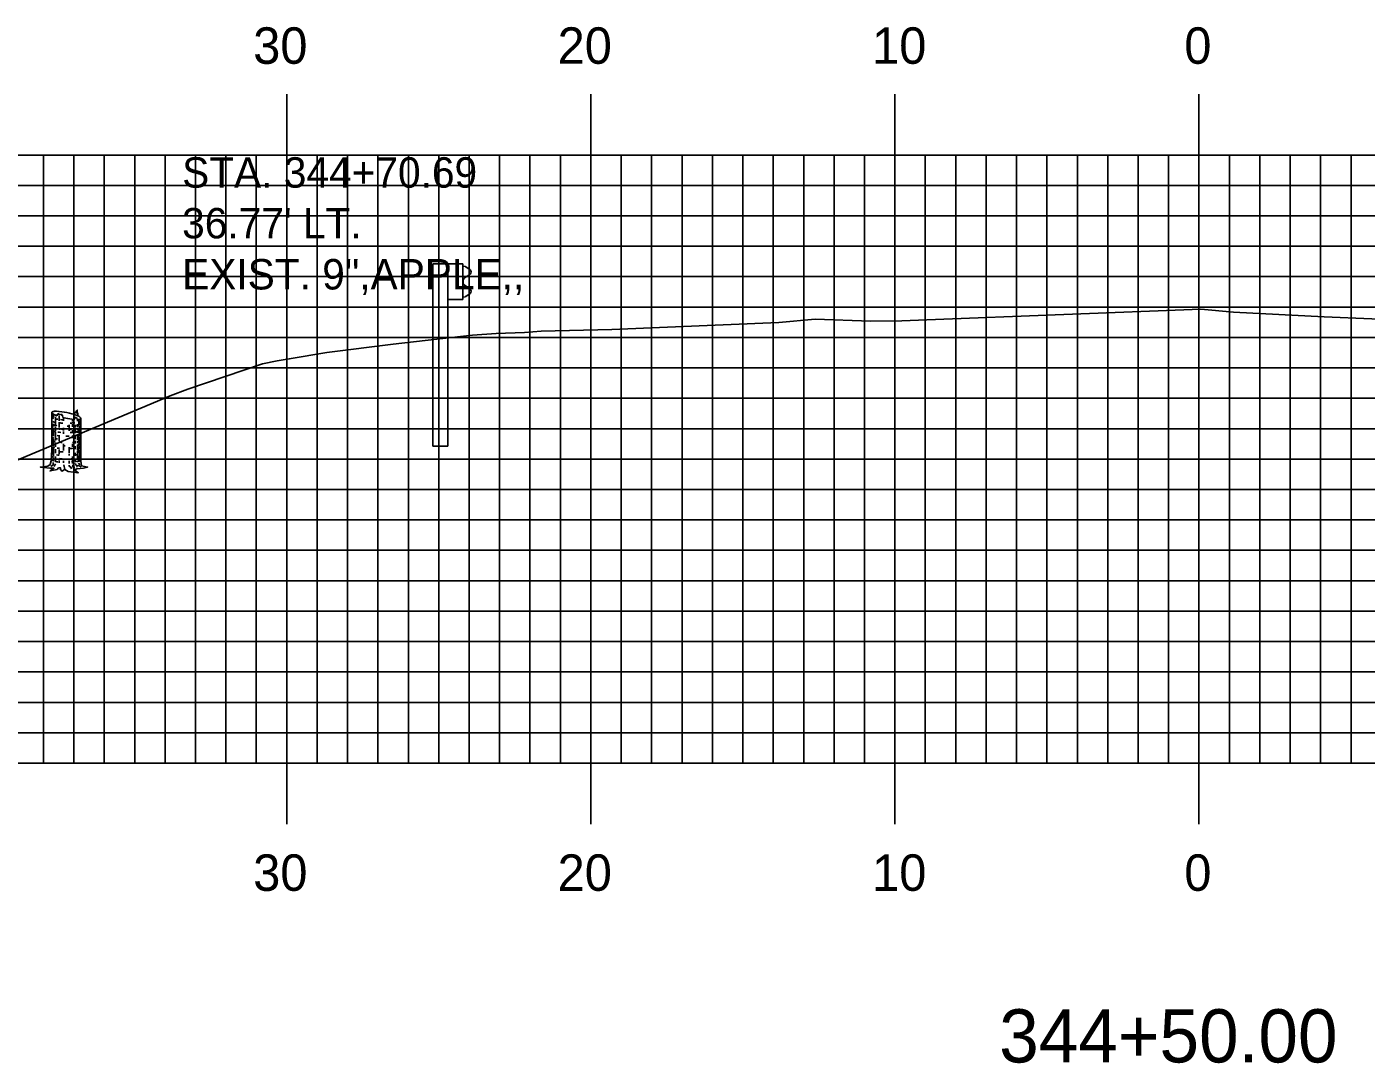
# Model space of a CAD drawing. Extents: x 1825540 to 1825883, y 442591 to 442811.
# Drawn here: x 1825667.33 to 1825711.37, y 442648.8 to 442682.88 of the extents above; entities that cross this region are included whole.
import ezdxf

# ---------------------------------------------------------------- set-up
doc = ezdxf.new("R2010")
doc.units = 0
for name, color, linetype in [('D_Text_Monospaced', 7, 'Continuous'), ('H_V ANNOTATION', 7, 'Continuous'), ('MAJOR', 7, 'Continuous'), ('MINOR', 7, 'Continuous'), ('S_Guardrail_Beam', 7, 'Continuous'), ('S_Roadway_Centerline', 7, 'Continuous'), ('S_Trees_Decid_NonPay', 7, 'Continuous')]:
    doc.layers.add(name, color=color, linetype=linetype)

msp = doc.modelspace()

# ---------------------------------------------------------------- linework, layer by layer
at = {"layer": 'MAJOR'}
for p, q in [((1825675.874, 442680.669), (1825675.874, 442678.665)), ((1825685.874, 442680.669), (1825685.874, 442678.665)), ((1825695.874, 442680.669), (1825695.874, 442678.665)), ((1825705.874, 442680.669), (1825705.874, 442678.665)), ((1825565.874, 442678.665), (1825845.874, 442678.665)), ((1825565.874, 442678.665), (1825845.874, 442678.665)), ((1825675.874, 442658.665), (1825675.874, 442678.665)), ((1825685.874, 442658.665), (1825685.874, 442678.665)), ((1825695.874, 442658.665), (1825695.874, 442678.665)), ((1825705.874, 442658.665), (1825705.874, 442678.665)), ((1825565.874, 442673.665), (1825845.874, 442673.665)), ((1825565.874, 442668.665), (1825845.874, 442668.665)), ((1825565.874, 442663.665), (1825845.874, 442663.665)), ((1825565.874, 442658.665), (1825845.874, 442658.665)), ((1825565.874, 442658.665), (1825845.874, 442658.665)), ((1825675.874, 442656.661), (1825675.874, 442658.665)), ((1825685.874, 442656.661), (1825685.874, 442658.665)), ((1825695.874, 442656.661), (1825695.874, 442658.665)), ((1825705.874, 442656.661), (1825705.874, 442658.665))]:
    msp.add_line(p, q, dxfattribs=at)
at = {"layer": 'MINOR'}
for p, q in [((1825667.874, 442658.665), (1825667.874, 442678.665)), ((1825668.874, 442658.665), (1825668.874, 442678.665)), ((1825669.874, 442658.665), (1825669.874, 442678.665)), ((1825670.874, 442658.665), (1825670.874, 442678.665)), ((1825671.874, 442658.665), (1825671.874, 442678.665)), ((1825672.874, 442658.665), (1825672.874, 442678.665)), ((1825673.874, 442658.665), (1825673.874, 442678.665)), ((1825674.874, 442658.665), (1825674.874, 442678.665)), ((1825676.874, 442658.665), (1825676.874, 442678.665)), ((1825677.874, 442658.665), (1825677.874, 442678.665)), ((1825678.874, 442658.665), (1825678.874, 442678.665)), ((1825679.874, 442658.665), (1825679.874, 442678.665)), ((1825680.874, 442658.665), (1825680.874, 442678.665)), ((1825681.874, 442658.665), (1825681.874, 442678.665)), ((1825682.874, 442658.665), (1825682.874, 442678.665)), ((1825683.874, 442658.665), (1825683.874, 442678.665)), ((1825684.874, 442658.665), (1825684.874, 442678.665)), ((1825686.874, 442658.665), (1825686.874, 442678.665)), ((1825687.874, 442658.665), (1825687.874, 442678.665)), ((1825688.874, 442658.665), (1825688.874, 442678.665)), ((1825689.874, 442658.665), (1825689.874, 442678.665)), ((1825690.874, 442658.665), (1825690.874, 442678.665)), ((1825691.874, 442658.665), (1825691.874, 442678.665)), ((1825692.874, 442658.665), (1825692.874, 442678.665)), ((1825693.874, 442658.665), (1825693.874, 442678.665)), ((1825694.874, 442658.665), (1825694.874, 442678.665)), ((1825696.874, 442658.665), (1825696.874, 442678.665)), ((1825697.874, 442658.665), (1825697.874, 442678.665)), ((1825698.874, 442658.665), (1825698.874, 442678.665)), ((1825699.874, 442658.665), (1825699.874, 442678.665)), ((1825700.874, 442658.665), (1825700.874, 442678.665)), ((1825701.874, 442658.665), (1825701.874, 442678.665)), ((1825702.874, 442658.665), (1825702.874, 442678.665)), ((1825703.874, 442658.665), (1825703.874, 442678.665)), ((1825704.874, 442658.665), (1825704.874, 442678.665)), ((1825706.874, 442658.665), (1825706.874, 442678.665)), ((1825707.874, 442658.665), (1825707.874, 442678.665)), ((1825708.874, 442658.665), (1825708.874, 442678.665)), ((1825709.874, 442658.665), (1825709.874, 442678.665)), ((1825710.874, 442658.665), (1825710.874, 442678.665)), ((1825565.874, 442677.665), (1825845.874, 442677.665)), ((1825565.874, 442676.665), (1825845.874, 442676.665)), ((1825565.874, 442675.665), (1825845.874, 442675.665)), ((1825565.874, 442674.665), (1825845.874, 442674.665)), ((1825565.874, 442672.665), (1825845.874, 442672.665)), ((1825565.874, 442671.665), (1825845.874, 442671.665)), ((1825565.874, 442670.665), (1825845.874, 442670.665)), ((1825565.874, 442669.665), (1825845.874, 442669.665)), ((1825565.874, 442667.665), (1825845.874, 442667.665)), ((1825565.874, 442666.665), (1825845.874, 442666.665)), ((1825565.874, 442665.665), (1825845.874, 442665.665)), ((1825565.874, 442664.665), (1825845.874, 442664.665)), ((1825565.874, 442662.665), (1825845.874, 442662.665)), ((1825565.874, 442661.665), (1825845.874, 442661.665)), ((1825565.874, 442660.665), (1825845.874, 442660.665)), ((1825565.874, 442659.665), (1825845.874, 442659.665))]:
    msp.add_line(p, q, dxfattribs=at)
at = {"layer": 'S_Guardrail_Beam'}
for p, q in [((1825680.68, 442675.086), (1825680.68, 442669.086)), ((1825681.172, 442675.086), (1825680.68, 442675.086)), ((1825681.662, 442675.086), (1825681.172, 442675.086)), ((1825681.172, 442675.086), (1825681.172, 442673.919)), ((1825681.662, 442673.919), (1825681.662, 442675.086)), ((1825681.662, 442675.013), (1825681.744, 442674.999)), ((1825681.904, 442674.749), (1825681.708, 442674.613)), ((1825681.76, 442674.992), (1825681.904, 442674.892)), ((1825681.675, 442674.548), (1825681.675, 442674.457)), ((1825681.708, 442674.393), (1825681.904, 442674.257)), ((1825681.172, 442669.086), (1825681.172, 442673.919)), ((1825681.172, 442673.919), (1825681.662, 442673.919)), ((1825681.744, 442674.007), (1825681.662, 442673.992)), ((1825681.904, 442674.114), (1825681.76, 442674.014)), ((1825681.172, 442669.086), (1825680.68, 442669.086))]:
    msp.add_line(p, q, dxfattribs=at)
for centre, major_axis, start_param, end_param in [((1825681.737, 442674.958), (0.0417, 0), 0.959931, 1.396263), ((1825681.854, 442674.82), (0.0877, 0), 5.323254, 7.243116), ((1825681.754, 442674.548), (-0.0789, 0), 5.323254, 6.283185), ((1825681.754, 442674.457), (-0.0789, 0), 6.283185, 7.243116), ((1825681.854, 442674.185), (0.0877, 0), 5.323254, 7.243116), ((1825681.737, 442674.048), (0.0417, 0), 4.886922, 5.323254)]:
    msp.add_ellipse(centre, major_axis=major_axis, ratio=0.995501, start_param=start_param, end_param=end_param, dxfattribs=at)
at = {"layer": 'S_Roadway_Centerline'}
msp.add_lwpolyline([(1825664.184, 442667.447), (1825672.039, 442670.745), (1825672.623, 442670.97), (1825675.076, 442671.797), (1825675.564, 442671.9), (1825675.957, 442671.958), (1825677.193, 442672.176), (1825679.372, 442672.44), (1825680.812, 442672.609), (1825681.981, 442672.739), (1825682.761, 442672.799), (1825683.698, 442672.826), (1825684.241, 442672.869), (1825686.568, 442672.931), (1825692.058, 442673.155), (1825693.251, 442673.263), (1825695.078, 442673.202), (1825696.1, 442673.21), (1825696.925, 442673.248), (1825705.934, 442673.591), (1825707.009, 442673.494), (1825709.987, 442673.349), (1825713.123, 442673.21)], dxfattribs=at)
at = {"layer": 'S_Trees_Decid_NonPay'}
for p, q in [((1825668.201, 442670.144), (1825668.201, 442670.049)), ((1825668.201, 442669.823), (1825668.201, 442669.74)), ((1825668.269, 442670.057), (1825668.269, 442669.756)), ((1825668.388, 442670.074), (1825668.388, 442669.926)), ((1825668.388, 442669.878), (1825668.388, 442669.709)), ((1825668.535, 442670.028), (1825668.535, 442669.921)), ((1825668.715, 442669.792), (1825668.715, 442669.592)), ((1825668.832, 442669.976), (1825668.832, 442669.897)), ((1825668.832, 442669.81), (1825668.832, 442669.726)), ((1825668.919, 442669.792), (1825668.919, 442669.705)), ((1825668.99, 442669.965), (1825668.99, 442669.913)), ((1825668.99, 442669.81), (1825668.99, 442669.728)), ((1825669.032, 442669.97), (1825669.032, 442669.752)), ((1825669.059, 442669.9), (1825669.059, 442669.818)), ((1825668.201, 442669.67), (1825668.201, 442669.419)), ((1825668.201, 442669.336), (1825668.201, 442669.106)), ((1825668.269, 442669.728), (1825668.269, 442669.596)), ((1825668.269, 442669.562), (1825668.269, 442669.281)), ((1825668.388, 442669.403), (1825668.388, 442669.254)), ((1825668.535, 442669.693), (1825668.535, 442669.606)), ((1825668.535, 442669.571), (1825668.535, 442669.501)), ((1825668.832, 442669.615), (1825668.832, 442669.514)), ((1825668.832, 442669.429), (1825668.832, 442669.353)), ((1825668.919, 442669.635), (1825668.919, 442669.514)), ((1825668.919, 442669.438), (1825668.919, 442669.324)), ((1825668.99, 442669.693), (1825668.99, 442669.619)), ((1825668.99, 442669.592), (1825668.99, 442669.532)), ((1825668.99, 442669.479), (1825668.99, 442669.298)), ((1825669.032, 442669.684), (1825669.032, 442669.532)), ((1825669.032, 442669.427), (1825669.032, 442669.349)), ((1825669.059, 442669.749), (1825669.059, 442669.619)), ((1825669.059, 442669.596), (1825669.059, 442669.415)), ((1825669.059, 442669.367), (1825669.059, 442669.121)), ((1825668.201, 442669.036), (1825668.201, 442668.875)), ((1825668.269, 442669.211), (1825668.269, 442669.067)), ((1825668.269, 442668.997), (1825668.269, 442668.855)), ((1825668.388, 442668.985), (1825668.388, 442668.832)), ((1825668.535, 442669.168), (1825668.535, 442668.945)), ((1825668.715, 442669.054), (1825668.715, 442668.867)), ((1825668.832, 442669.168), (1825668.832, 442669.071)), ((1825668.919, 442669.262), (1825668.919, 442669.18)), ((1825668.919, 442669.094), (1825668.919, 442668.997)), ((1825668.99, 442669.266), (1825668.99, 442669.184)), ((1825668.99, 442669.13), (1825668.99, 442668.96)), ((1825668.99, 442668.926), (1825668.99, 442668.647)), ((1825669.032, 442669.322), (1825669.032, 442669.215)), ((1825669.032, 442669.18), (1825669.032, 442669.079)), ((1825669.032, 442669.054), (1825669.032, 442668.871)), ((1825669.059, 442669.102), (1825669.059, 442669.007)), ((1825669.061, 442668.954), (1825669.06, 442668.694)), ((1825668.201, 442668.859), (1825668.201, 442668.754)), ((1825668.201, 442668.717), (1825668.201, 442668.593)), ((1825668.268, 442668.513), (1825668.227, 442668.417)), ((1825668.269, 442668.754), (1825668.269, 442668.573)), ((1825668.388, 442668.62), (1825668.388, 442668.542)), ((1825668.535, 442668.612), (1825668.535, 442668.546)), ((1825668.575, 442668.326), (1825668.54, 442668.472)), ((1825668.715, 442668.836), (1825668.715, 442668.783)), ((1825668.715, 442668.607), (1825668.715, 442668.517)), ((1825668.832, 442668.746), (1825668.832, 442668.522)), ((1825668.919, 442668.867), (1825668.919, 442668.768)), ((1825668.919, 442668.639), (1825668.919, 442668.581)), ((1825668.99, 442668.594), (1825668.99, 442668.569)), ((1825669.03, 442668.529), (1825669.065, 442668.478)), ((1825669.032, 442668.768), (1825669.032, 442668.577)), ((1825669.059, 442668.655), (1825669.059, 442668.581)), ((1825669.112, 442668.408), (1825669.045, 442668.439))]:
    msp.add_line(p, q, dxfattribs=at)
for points in [[(1825669.005, 442670.088), (1825669.001, 442670.183), (1825668.987, 442670.156), (1825668.987, 442670.277), (1825668.966, 442670.214), (1825668.952, 442670.247), (1825668.935, 442670.191), (1825668.919, 442670.208), (1825668.9, 442670.199), (1825668.881, 442670.132)], [(1825669.1, 442670.008), (1825669.1, 442668.596), (1825669.123, 442668.447), (1825669.326, 442668.404), (1825669.186, 442668.369), (1825668.968, 442668.35), (1825668.898, 442668.307), (1825669.02, 442668.218), (1825668.688, 442668.262), (1825668.575, 442668.326), (1825668.482, 442668.266), (1825668.427, 442668.344), (1825668.435, 442668.381), (1825668.373, 442668.383), (1825668.322, 442668.326), (1825668.089, 442668.274), (1825668.217, 442668.363), (1825668.085, 442668.365), (1825667.776, 442668.402), (1825668.015, 442668.433), (1825668.093, 442668.491), (1825668.132, 442668.612), (1825668.149, 442668.966), (1825668.149, 442670.199)], [(1825668.513, 442670.033), (1825668.505, 442670.1), (1825668.48, 442670.105), (1825668.472, 442670.14), (1825668.441, 442670.125), (1825668.427, 442670.14), (1825668.402, 442670.117), (1825668.379, 442670.125), (1825668.367, 442670.174), (1825668.359, 442670.131), (1825668.328, 442670.14), (1825668.325, 442670.088)], [(1825668.983, 442669.964), (1825668.966, 442670.026), (1825668.944, 442670.014), (1825668.913, 442670.049), (1825668.879, 442669.971)], [(1825668.198, 442668.55), (1825668.19, 442668.474), (1825668.112, 442668.424)], [(1825668.723, 442668.468), (1825668.723, 442668.431), (1825668.774, 442668.4), (1825668.791, 442668.35)], [(1825668.835, 442668.474), (1825668.841, 442668.404), (1825668.904, 442668.392)], [(1825668.982, 442668.439), (1825668.939, 442668.474), (1825668.931, 442668.522)], [(1825669.061, 442668.455), (1825668.982, 442668.439), (1825668.966, 442668.396)]]:
    msp.add_lwpolyline(points, dxfattribs=at)
for centre, radius, start, end in [((1825668.18, 442670.19), 0.0336, 119.396, 138.1723), ((1825668.209, 442670.138), 0.0935, 108.1723, 119.396), ((1825668.28, 442669.921), 0.322, 86.0543, 108.1723), ((1825668.13, 442667.741), 2.507, 78.1723, 86.0543), ((1825668.167, 442670.199), 0.0179, 168.1723, 184.2278), ((1825668.173, 442670.2), 0.0237, 184.2278, 198.1723), ((1825668.168, 442670.052), 0.0191, 163.9485, 180), ((1825668.168, 442670.052), 0.0191, 180, 196.0515), ((1825668.174, 442670.054), 0.0252, 196.0515, 210), ((1825668.168, 442669.838), 0.0191, 163.9485, 180), ((1825668.168, 442669.838), 0.0191, 180, 196.0515), ((1825668.174, 442669.84), 0.0252, 196.0515, 210), ((1825668.167, 442670.199), 0.0179, 152.1168, 168.1723), ((1825668.182, 442670.203), 0.0336, 198.1723, 216.9486), ((1825668.172, 442670.197), 0.0237, 138.1723, 152.1168), ((1825668.183, 442670.059), 0.0356, 210, 228.7494), ((1825668.183, 442669.845), 0.0356, 210, 228.7494), ((1825668.23, 442670.239), 0.0935, 216.9486, 228.1723), ((1825668.224, 442670.106), 0.0984, 228.7494, 240), ((1825668.224, 442669.892), 0.0984, 228.7494, 240), ((1825668.383, 442670.409), 0.322, 228.1723, 250.2902), ((1825668.338, 442670.303), 0.326, 240, 248.3243), ((1825668.338, 442670.089), 0.326, 240, 243.5719), ((1825668.338, 442670.19), 0.326, 240.9099, 257.8036), ((1825668.338, 442670.089), 0.326, 250.4167, 261.8968), ((1825668.338, 442670.303), 0.326, 257.8036, 261.8968), ((1825669.119, 442672.466), 2.507, 250.2902, 251.5281), ((1825668.624, 442672.313), 2.356, 261.8968, 263.2799), ((1825668.624, 442672.2), 2.356, 264.242, 267.3673), ((1825668.624, 442672.313), 2.356, 265.24, 267.8386), ((1825669.119, 442672.466), 2.507, 255.9987, 258.1723), ((1825669.119, 442672.466), 2.507, 258.1723, 264.5013), ((1825668.13, 442667.741), 2.507, 70.2902, 78.1723), ((1825668.624, 442672.2), 2.356, 273.1481, 276.7734), ((1825668.867, 442669.798), 0.322, 48.1723, 70.2902), ((1825668.969, 442670.286), 0.322, 272.4479, 288.1723), ((1825668.91, 442670.19), 0.326, 291.9506, 300), ((1825668.91, 442670.089), 0.326, 291.9506, 300), ((1825669.04, 442670.069), 0.0935, 288.1723, 299.396), ((1825669.024, 442669.993), 0.0984, 300, 311.2506), ((1825669.024, 442669.892), 0.0984, 300, 311.2506), ((1825669.019, 442669.968), 0.0935, 36.9486, 48.1723), ((1825669.07, 442670.017), 0.0336, 299.396, 318.1723), ((1825669.065, 442669.946), 0.0356, 311.2506, 330), ((1825669.065, 442669.845), 0.0356, 311.2506, 330), ((1825669.067, 442670.004), 0.0336, 18.1723, 36.9486), ((1825669.077, 442670.01), 0.0237, 318.1723, 332.1168), ((1825669.074, 442669.94), 0.0252, 330, 343.9485), ((1825669.074, 442669.84), 0.0252, 330, 343.9485), ((1825669.082, 442670.008), 0.0179, 332.1168, 348.1723), ((1825669.076, 442670.007), 0.0237, 4.2278, 18.1723), ((1825669.08, 442669.939), 0.0191, 360, 6.1128), ((1825669.08, 442669.939), 0.0191, 343.9485, 360), ((1825669.08, 442669.838), 0.0191, 360, 6.1128), ((1825669.08, 442669.838), 0.0191, 343.9485, 360), ((1825669.082, 442670.008), 0.0179, 348.1723, 4.2278), ((1825668.168, 442669.735), 0.0191, 163.9485, 180), ((1825668.168, 442669.735), 0.0191, 180, 196.0515), ((1825668.174, 442669.737), 0.0252, 196.0515, 210), ((1825668.168, 442669.515), 0.0191, 163.9485, 180), ((1825668.168, 442669.515), 0.0191, 180, 196.0515), ((1825668.174, 442669.517), 0.0252, 196.0515, 210), ((1825668.168, 442669.4), 0.0191, 163.9485, 180), ((1825668.168, 442669.4), 0.0191, 180, 196.0515), ((1825668.174, 442669.402), 0.0252, 196.0515, 210), ((1825668.183, 442669.742), 0.0356, 210, 228.7494), ((1825668.183, 442669.522), 0.0356, 210, 228.7494), ((1825668.183, 442669.407), 0.0356, 210, 228.7494), ((1825668.224, 442669.789), 0.0984, 228.7494, 240), ((1825668.224, 442669.569), 0.0984, 228.7494, 240), ((1825668.225, 442669.455), 0.0984, 228.7494, 240), ((1825668.338, 442669.986), 0.326, 240, 243.243), ((1825668.338, 442669.766), 0.326, 240, 245.1545), ((1825668.339, 442669.652), 0.326, 240, 247.8656), ((1825668.338, 442669.881), 0.326, 245.1545, 257.8036), ((1825668.338, 442669.986), 0.326, 251.6831, 257.8036), ((1825668.339, 442669.652), 0.326, 257.6699, 261.8968), ((1825668.624, 442672.099), 2.356, 261.8968, 262.5519), ((1825668.624, 442671.776), 2.356, 262.6588, 264.7911), ((1825668.624, 442671.891), 2.356, 263.2682, 265.6362), ((1825668.624, 442671.996), 2.356, 263.3413, 264.9946), ((1825668.624, 442671.996), 2.356, 266.5036, 267.8386), ((1825668.624, 442671.776), 2.356, 269.5578, 270), ((1825668.624, 442671.776), 2.356, 270, 272.414), ((1825668.624, 442672.099), 2.356, 270.8119, 272.1981), ((1825668.624, 442671.996), 2.356, 272.1981, 273.9741), ((1825668.624, 442671.891), 2.356, 273.0067, 275.0647), ((1825668.624, 442672.099), 2.356, 275.0647, 278.1032), ((1825668.624, 442671.776), 2.356, 275.0647, 277.1868), ((1825668.624, 442671.891), 2.356, 277.1868, 278.1032), ((1825668.624, 442671.996), 2.356, 277.3838, 278.1032), ((1825668.91, 442670.089), 0.326, 278.1032, 279.0854), ((1825668.91, 442669.986), 0.326, 278.1032, 284.0382), ((1825668.91, 442669.881), 0.326, 278.1032, 284.0382), ((1825668.91, 442669.766), 0.326, 284.0382, 300), ((1825668.911, 442669.652), 0.326, 283.9036, 291.8098), ((1825668.91, 442669.881), 0.326, 291.9506, 300), ((1825668.911, 442669.652), 0.326, 297.0058, 300), ((1825669.024, 442669.684), 0.0984, 300, 311.2506), ((1825669.024, 442669.569), 0.0984, 300, 311.2506), ((1825669.025, 442669.455), 0.0984, 300, 311.2506), ((1825669.065, 442669.637), 0.0356, 311.2506, 330), ((1825669.065, 442669.522), 0.0356, 311.2506, 330), ((1825669.066, 442669.407), 0.0356, 311.2506, 330), ((1825669.074, 442669.632), 0.0252, 330, 343.9485), ((1825669.074, 442669.517), 0.0252, 330, 343.9485), ((1825669.075, 442669.402), 0.0252, 330, 343.9485), ((1825669.08, 442669.735), 0.0191, 360, 6.1128), ((1825669.08, 442669.735), 0.0191, 343.9485, 360), ((1825669.08, 442669.63), 0.0191, 360, 6.1128), ((1825669.08, 442669.63), 0.0191, 343.9485, 360), ((1825669.08, 442669.515), 0.0191, 360, 6.1128), ((1825669.08, 442669.515), 0.0191, 343.9485, 360), ((1825669.081, 442669.4), 0.0191, 343.9485, 360), ((1825669.081, 442669.4), 0.0191, 0, 6.1128), ((1825668.165, 442669.3), 0.0191, 163.9485, 180), ((1825668.168, 442669.195), 0.0191, 163.9485, 180), ((1825668.168, 442669.195), 0.0191, 180, 196.0515), ((1825668.174, 442669.197), 0.0252, 196.0515, 210), ((1825668.183, 442669.202), 0.0356, 210, 228.7494), ((1825668.224, 442669.25), 0.0984, 228.7494, 240), ((1825668.335, 442669.551), 0.326, 240, 256.9079), ((1825668.338, 442669.447), 0.326, 240, 245.1545), ((1825668.338, 442669.356), 0.326, 241.939, 253.9183), ((1825668.625, 442671.662), 2.356, 261.8968, 262.8615), ((1825668.624, 442671.366), 2.356, 262.5843, 264.4865), ((1825668.624, 442671.253), 2.356, 264.242, 267.469), ((1825668.622, 442671.562), 2.356, 264.3443, 266.8529), ((1825668.624, 442671.457), 2.356, 267.8386, 269.0054), ((1825668.624, 442671.366), 2.356, 272.1981, 275.2726), ((1825668.622, 442671.562), 2.356, 274.9734, 277.2455), ((1825668.624, 442671.457), 2.356, 275.0647, 276.428), ((1825668.91, 442669.447), 0.326, 284.0382, 291.9506), ((1825668.91, 442669.243), 0.326, 284.0382, 291.9506), ((1825668.908, 442669.551), 0.326, 292.4049, 300), ((1825668.91, 442669.447), 0.326, 297.1525, 300), ((1825669.022, 442669.354), 0.0984, 300, 311.2506), ((1825669.024, 442669.25), 0.0984, 300, 311.2506), ((1825669.063, 442669.307), 0.0356, 311.2506, 330), ((1825669.065, 442669.202), 0.0356, 311.2506, 330), ((1825669.072, 442669.302), 0.0252, 330, 343.9485), ((1825669.078, 442669.3), 0.0191, 343.9485, 360), ((1825669.074, 442669.197), 0.0252, 330, 343.9485), ((1825669.078, 442669.3), 0.0191, 0, 6.1128), ((1825669.08, 442669.195), 0.0191, 360, 6.1128), ((1825669.08, 442669.195), 0.0191, 343.9485, 360), ((1825669.08, 442669.105), 0.0191, 360, 6.1128), ((1825668.153, 442668.656), 0.0191, 163.9485, 180), ((1825668.153, 442668.656), 0.0191, 180, 196.0515), ((1825668.159, 442668.657), 0.0252, 196.0515, 210), ((1825668.168, 442668.662), 0.0356, 210, 228.7494), ((1825668.159, 442668.766), 0.0191, 163.9485, 180), ((1825668.159, 442668.766), 0.0191, 180, 196.0515), ((1825668.165, 442668.767), 0.0252, 196.0515, 210), ((1825668.174, 442668.773), 0.0356, 210, 228.7494), ((1825668.164, 442668.876), 0.0191, 163.9485, 180), ((1825668.164, 442668.876), 0.0191, 180, 196.0515), ((1825668.169, 442668.878), 0.0252, 196.0515, 210), ((1825668.21, 442668.71), 0.0984, 228.7494, 240), ((1825668.178, 442668.883), 0.0356, 210, 228.7494), ((1825668.215, 442668.82), 0.0984, 228.7494, 240), ((1825668.22, 442668.931), 0.0984, 228.7494, 240), ((1825668.323, 442668.907), 0.326, 240, 247.9161), ((1825668.329, 442669.017), 0.326, 240, 241.9097), ((1825668.334, 442669.128), 0.326, 240, 245.9375), ((1825668.323, 442668.907), 0.326, 260.3834, 261.8968), ((1825668.61, 442670.917), 2.356, 261.8968, 263.5333), ((1825668.62, 442671.138), 2.356, 262.2226, 264.4852), ((1825668.615, 442671.027), 2.356, 264.9089, 266.8158), ((1825668.615, 442671.027), 2.356, 274.1864, 275.2829), ((1825668.61, 442670.917), 2.356, 274.5551, 275.4167), ((1825668.62, 442671.138), 2.356, 277.2863, 278.1032), ((1825668.61, 442670.917), 2.356, 277.5403, 278.1032), ((1825668.896, 442668.907), 0.326, 278.1032, 294.7094), ((1825668.906, 442669.128), 0.326, 278.1032, 284.7741), ((1825668.901, 442669.017), 0.326, 293.6544, 300), ((1825669.01, 442668.71), 0.0984, 300, 311.2506), ((1825669.02, 442668.931), 0.0984, 300, 311.2506), ((1825669.051, 442668.662), 0.0356, 311.2506, 330), ((1825669.06, 442668.657), 0.0252, 330, 343.9485), ((1825669.066, 442668.656), 0.0191, 343.9485, 360), ((1825669.061, 442668.883), 0.0356, 311.2506, 330), ((1825669.066, 442668.656), 0.0191, 0, 6.1128), ((1825669.07, 442668.878), 0.0252, 330, 343.9485), ((1825669.076, 442668.876), 0.0191, 360, 6.1128), ((1825669.076, 442668.876), 0.0191, 343.9485, 360)]:
    msp.add_arc(centre, radius, start, end, dxfattribs=at)

# ---------------------------------------------------------------- texts
at = {"layer": 'D_Text_Monospaced'}
for s, height, p in [('STA. 344+70.69', 0.99996, (1825672.434, 442677.592)), ("36.77' LT.", 1, (1825672.434, 442675.924)), ('EXIST. 9",APPLE,,', 0.99996, (1825672.434, 442674.244))]:
    msp.add_text(s, height=height, dxfattribs=at).set_placement(p)
at = {"layer": 'H_V ANNOTATION'}
for s, height, p in [('30', 1.2, (1825674.771, 442681.665)), ('20', 1.2, (1825684.782, 442681.665)), ('10', 1.2, (1825695.125, 442681.665)), ('0', 1.2, (1825705.392, 442681.665)), ('30', 1.2, (1825674.771, 442654.465)), ('20', 1.2, (1825684.782, 442654.465)), ('10', 1.2, (1825695.125, 442654.465)), ('0', 1.2, (1825705.392, 442654.465)), ('344+50.00', 1.75, (1825699.304, 442648.821))]:
    msp.add_text(s, height=height, dxfattribs=at).set_placement(p)
at = {"layer": 'S_Roadway_Centerline'}
for s, p in [('L', (1825705.925, 442673.584)), ('C', (1825705.929, 442673.591))]:
    msp.add_text(s, height=0.0146, dxfattribs=at).set_placement(p)

doc.saveas('drawing.dxf')
